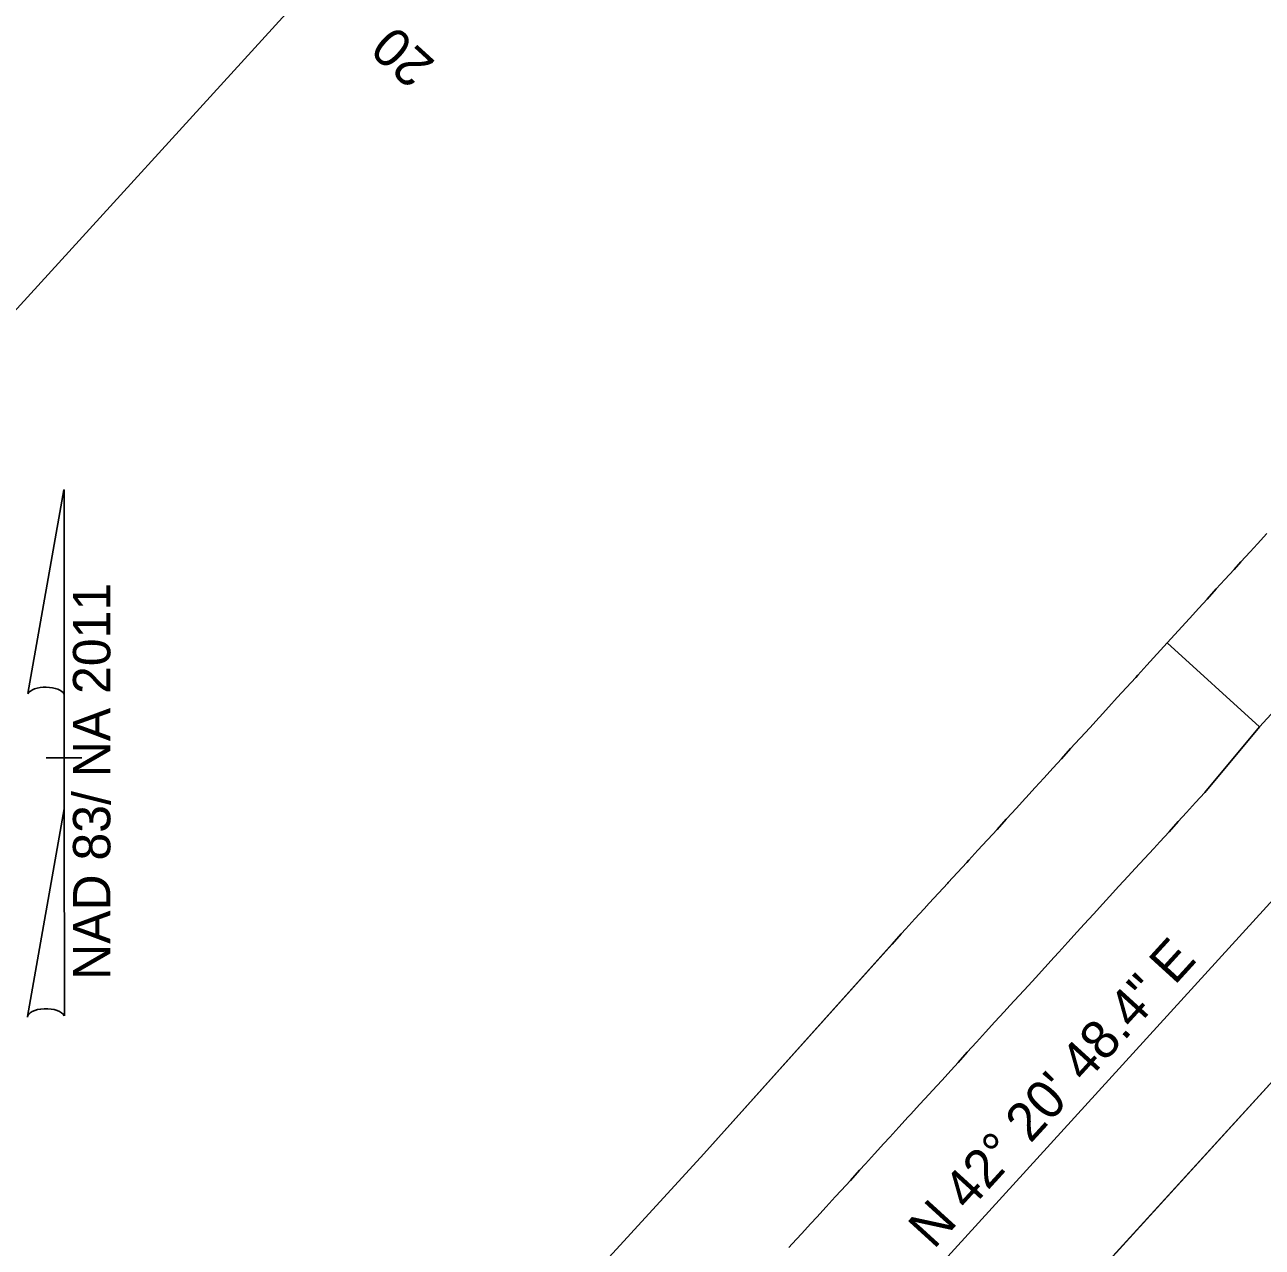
# Model space of a CAD drawing. Extents: x 1807040 to 1808827, y 913493 to 915218.
# Drawn here: x 1807478.3 to 1807703.5, y 914441.7 to 914664.2 of the extents above; entities that cross this region are included whole.
import ezdxf

# ---------------------------------------------------------------- set-up
doc = ezdxf.new("R2010")
doc.units = 0
for name, color, linetype in [('Prop EOT', 7, 'Continuous'), ('Prop Horizontal Alignment Direction Label', 7, 'Continuous'), ('Prop Horizontal Alignment Tick Label', 7, 'Continuous'), ('Prop North Arrow NAD83 for Plan Sheets CELL', 7, 'Continuous'), ('Scratch_Level_0', 7, 'Continuous'), ('Scratch_Level_1', 7, 'Continuous'), ('Scratch_Level_3', 7, 'Continuous')]:
    doc.layers.add(name, color=color, linetype=linetype)

msp = doc.modelspace()

# ---------------------------------------------------------------- linework, layer by layer
at = {"layer": 'Prop EOT'}
for p, q in [((1807702.96, 914536.44), (1808029.68, 914894.91)), ((1807613.95, 914371.74), (1808063.17, 914864.38))]:
    msp.add_line(p, q, dxfattribs=at)
for points in [[(1807686.17, 914551.74), (1807690.2, 914556.18), (1807691.89, 914558.02), (1807693.42, 914559.69), (1807695.09, 914561.55), (1807696.63, 914563.25), (1807698.32, 914565.1), (1807699.58, 914566.48), (1807701.28, 914568.32), (1807702.61, 914569.75), (1807704.27, 914571.63)], [(1807601.83, 914458.72), (1807637.77, 914498.74), (1807638.58, 914499.64), (1807640.27, 914501.49), (1807641.96, 914503.33), (1807642.85, 914504.31), (1807644.54, 914506.15), (1807646.24, 914507.98), (1807646.33, 914508.08), (1807648.01, 914509.93), (1807649.7, 914511.77), (1807650.04, 914512.14), (1807651.73, 914513.99), (1807653.42, 914515.83), (1807653.51, 914515.92), (1807655.2, 914517.77), (1807656.89, 914519.61), (1807657, 914519.73), (1807658.68, 914521.58), (1807660.36, 914523.43), (1807660.46, 914523.54), (1807662.15, 914525.39), (1807663.71, 914527.11), (1807665.39, 914528.97), (1807666.9, 914530.64), (1807668.59, 914532.48), (1807670.28, 914534.31), (1807670.4, 914534.44), (1807672.08, 914536.28), (1807673.77, 914538.13), (1807673.86, 914538.22), (1807675.53, 914540.08), (1807677.05, 914541.77), (1807678.74, 914543.6), (1807680.44, 914545.44), (1807680.8, 914545.83), (1807682.48, 914547.68), (1807686.17, 914551.74)], [(1807617.33, 914441.65), (1807617.95, 914442.33), (1807619.64, 914444.17), (1807621.33, 914446.02), (1807622.4, 914447.18), (1807624.09, 914449.03), (1807625.77, 914450.88), (1807626.83, 914452.04), (1807628.51, 914453.88), (1807630.2, 914455.73), (1807631.25, 914456.88), (1807632.93, 914458.73), (1807634.62, 914460.58), (1807635.67, 914461.73), (1807637.35, 914463.58), (1807639.03, 914465.43), (1807639.45, 914465.89), (1807641.15, 914467.72), (1807642.85, 914469.56), (1807643.47, 914470.24), (1807645.16, 914472.08), (1807646.84, 914473.93), (1807648.11, 914475.33), (1807649.79, 914477.19), (1807651.46, 914479.04), (1807653.11, 914480.86), (1807654.8, 914482.71), (1807656.48, 914484.55), (1807657.54, 914485.71), (1807659.24, 914487.54), (1807660.94, 914489.38), (1807662.22, 914490.77), (1807663.9, 914492.62), (1807665.58, 914494.48), (1807666.43, 914495.42), (1807668.11, 914497.26), (1807669.8, 914499.11), (1807671.07, 914500.5), (1807672.75, 914502.35), (1807674.43, 914504.2), (1807675.68, 914505.58), (1807677.38, 914507.42), (1807679.07, 914509.26), (1807680.33, 914510.63), (1807682.03, 914512.47), (1807683.72, 914514.31), (1807684.8, 914515.5), (1807686.49, 914517.35), (1807688.17, 914519.19), (1807689.65, 914520.82), (1807691.34, 914522.66), (1807693.03, 914524.5), (1807702.96, 914536.44)], [(1807601.83, 914458.72), (1807507.53, 914355.72), (1807505.84, 914353.87), (1807504.15, 914352.03), (1807502.46, 914350.19), (1807500.78, 914348.34), (1807499.09, 914346.5), (1807497.4, 914344.65), (1807495.71, 914342.81), (1807494.02, 914340.97), (1807492.34, 914339.12), (1807490.65, 914337.28), (1807488.96, 914335.43), (1807487.37, 914333.69), (1807485.68, 914331.85), (1807483.99, 914330.01), (1807482.3, 914328.16), (1807480.61, 914326.32), (1807478.92, 914324.48), (1807477.23, 914322.63)]]:
    msp.add_lwpolyline(points, dxfattribs=at)
at = {"layer": 'Prop North Arrow NAD83 for Plan Sheets CELL'}
for p, q in [((1807478.85, 914542.49), (1807485.41, 914579.57)), ((1807485.45, 914579.57), (1807485.41, 914579.57)), ((1807485.45, 914579.57), (1807485.41, 914579.57)), ((1807485.45, 914579.57), (1807485.45, 914541.33)), ((1807485.45, 914521.49), (1807485.45, 914542.45)), ((1807485.45, 914541.33), (1807485.45, 914542.41)), ((1807482.25, 914530.77), (1807482.21, 914530.77)), ((1807485.09, 914530.77), (1807482.25, 914530.77)), ((1807482.29, 914530.77), (1807488.69, 914530.77)), ((1807485.45, 914521.49), (1807478.77, 914483.69)), ((1807485.49, 914483.85), (1807485.45, 914521.49))]:
    msp.add_line(p, q, dxfattribs=at)
for centre, start_param, end_param in [((1807482.16, 914542.09), 0.216388, 2.908219), ((1807482.16, 914483.56), 0.201328, 3.141593)]:
    msp.add_ellipse(centre, major_axis=(3.38, -0.02), ratio=0.461098, start_param=start_param, end_param=end_param, dxfattribs=at)
at = {"layer": 'Scratch_Level_0'}
for p, q in [((1807702.96, 914536.44), (1808029.68, 914894.91)), ((1808063.17, 914864.38), (1807658.9, 914421.03)), ((1807686.17, 914551.74), (1807682.48, 914547.68)), ((1807686.17, 914551.74), (1807702.96, 914536.44)), ((1807702.96, 914536.44), (1807686.17, 914551.74)), ((1807682.48, 914547.68), (1807680.8, 914545.83)), ((1807680.44, 914545.44), (1807678.74, 914543.6)), ((1807680.8, 914545.83), (1807680.44, 914545.44)), ((1807678.74, 914543.6), (1807677.05, 914541.77)), ((1807677.05, 914541.77), (1807675.53, 914540.08)), ((1807675.53, 914540.08), (1807673.86, 914538.22)), ((1807670.4, 914534.44), (1807670.28, 914534.31)), ((1807688.17, 914519.19), (1807689.65, 914520.82)), ((1807683.72, 914514.31), (1807684.8, 914515.5)), ((1807679.07, 914509.26), (1807680.33, 914510.63)), ((1807646.24, 914507.98), (1807644.54, 914506.15)), ((1807671.07, 914500.5), (1807672.75, 914502.35)), ((1807672.75, 914502.35), (1807674.43, 914504.2)), ((1807637.77, 914498.74), (1807636.1, 914496.88)), ((1807638.58, 914499.64), (1807637.77, 914498.74)), ((1807660.94, 914489.38), (1807662.22, 914490.77)), ((1807654.8, 914482.71), (1807656.48, 914484.55)), ((1807656.48, 914484.55), (1807657.54, 914485.71)), ((1807653.11, 914480.86), (1807654.8, 914482.71)), ((1807651.46, 914479.04), (1807653.11, 914480.86)), ((1807646.84, 914473.93), (1807648.11, 914475.33)), ((1807645.16, 914472.08), (1807646.84, 914473.93)), ((1807634.62, 914460.58), (1807635.67, 914461.73)), ((1807635.67, 914461.73), (1807637.35, 914463.58)), ((1807632.93, 914458.73), (1807634.62, 914460.58)), ((1807625.77, 914450.88), (1807626.83, 914452.04)), ((1807619.64, 914444.17), (1807621.33, 914446.02))]:
    msp.add_line(p, q, dxfattribs=at)
for points in [[(1807704.27, 914571.63), (1807702.61, 914569.75), (1807701.28, 914568.32), (1807699.58, 914566.48), (1807698.32, 914565.1), (1807696.63, 914563.25), (1807695.09, 914561.55), (1807693.42, 914559.69), (1807691.89, 914558.02), (1807690.2, 914556.18), (1807686.17, 914551.74)], [(1807673.86, 914538.22), (1807673.77, 914538.13), (1807672.08, 914536.28), (1807670.4, 914534.44)], [(1807689.65, 914520.82), (1807691.34, 914522.66), (1807693.03, 914524.5), (1807702.96, 914536.44)], [(1807670.28, 914534.31), (1807668.59, 914532.48), (1807666.9, 914530.64), (1807665.39, 914528.97)], [(1807665.39, 914528.97), (1807663.71, 914527.11), (1807662.15, 914525.39), (1807660.46, 914523.54), (1807660.36, 914523.43), (1807658.68, 914521.58), (1807657, 914519.73), (1807656.89, 914519.61)], [(1807656.89, 914519.61), (1807655.2, 914517.77), (1807653.51, 914515.92)], [(1807684.8, 914515.5), (1807686.49, 914517.35), (1807688.17, 914519.19)], [(1807653.51, 914515.92), (1807653.42, 914515.83), (1807651.73, 914513.99)], [(1807651.73, 914513.99), (1807650.04, 914512.14), (1807649.7, 914511.77), (1807648.01, 914509.93), (1807646.33, 914508.08), (1807646.24, 914507.98)], [(1807680.33, 914510.63), (1807682.03, 914512.47), (1807683.72, 914514.31)], [(1807674.43, 914504.2), (1807675.68, 914505.58), (1807677.38, 914507.42), (1807679.07, 914509.26)], [(1807644.54, 914506.15), (1807642.85, 914504.31), (1807641.96, 914503.33), (1807640.27, 914501.49), (1807638.58, 914499.64)], [(1807668.11, 914497.26), (1807669.8, 914499.11), (1807671.07, 914500.5)], [(1807636.1, 914496.88), (1807634.43, 914495.02), (1807601.83, 914458.72)], [(1807662.22, 914490.77), (1807663.9, 914492.62), (1807665.58, 914494.48), (1807666.43, 914495.42), (1807668.11, 914497.26)], [(1807657.54, 914485.71), (1807659.24, 914487.54), (1807660.94, 914489.38)], [(1807648.11, 914475.33), (1807649.79, 914477.19), (1807651.46, 914479.04)], [(1807642.85, 914469.56), (1807643.47, 914470.24), (1807645.16, 914472.08)], [(1807637.35, 914463.58), (1807639.03, 914465.43), (1807639.45, 914465.89), (1807641.15, 914467.72), (1807642.85, 914469.56)], [(1807601.83, 914458.72), (1807521.51, 914370.99), (1807521.03, 914370.47), (1807519.35, 914368.63), (1807517.66, 914366.78)], [(1807626.83, 914452.04), (1807628.51, 914453.88), (1807630.2, 914455.73), (1807631.25, 914456.88), (1807632.93, 914458.73)], [(1807621.33, 914446.02), (1807622.4, 914447.18), (1807624.09, 914449.03), (1807625.77, 914450.88)], [(1807617.33, 914441.65), (1807617.95, 914442.33), (1807619.64, 914444.17)]]:
    msp.add_lwpolyline(points, dxfattribs=at)
at = {"layer": 'Scratch_Level_1'}
msp.add_lwpolyline([(1807040.33, 914133.66), (1807040.33, 914133.66), (1807428.35, 913780.01), (1808256.27, 914688.39), (1807868.25, 915042.04)], close=True, dxfattribs=at)
at = {"layer": 'Scratch_Level_3'}
msp.add_line((1807238.34, 913992.52), (1808046.68, 914879.41), dxfattribs=at)

# ---------------------------------------------------------------- texts
at = {"layer": 'Prop Horizontal Alignment Direction Label'}
msp.add_text('N 42%%d 20\' 48.4" E', height=7, rotation=47.6532, dxfattribs=at).set_placement((1807643.68, 914441.18))
msp.add_text('N 42%%d 20\' 48.4" E', height=7, rotation=47.6532, dxfattribs=at).set_placement((1807643.68, 914441.18))
at = {"layer": 'Prop Horizontal Alignment Tick Label'}
msp.add_text('20', height=7, rotation=137.6532, dxfattribs=at).set_placement((1807553.2, 914657.4))
at = {"layer": 'Prop North Arrow NAD83 for Plan Sheets CELL'}
msp.add_text('NAD 83/ NA 2011', height=6.8, rotation=90, dxfattribs=at).set_placement((1807493.86, 914490.37))

doc.saveas('drawing.dxf')
